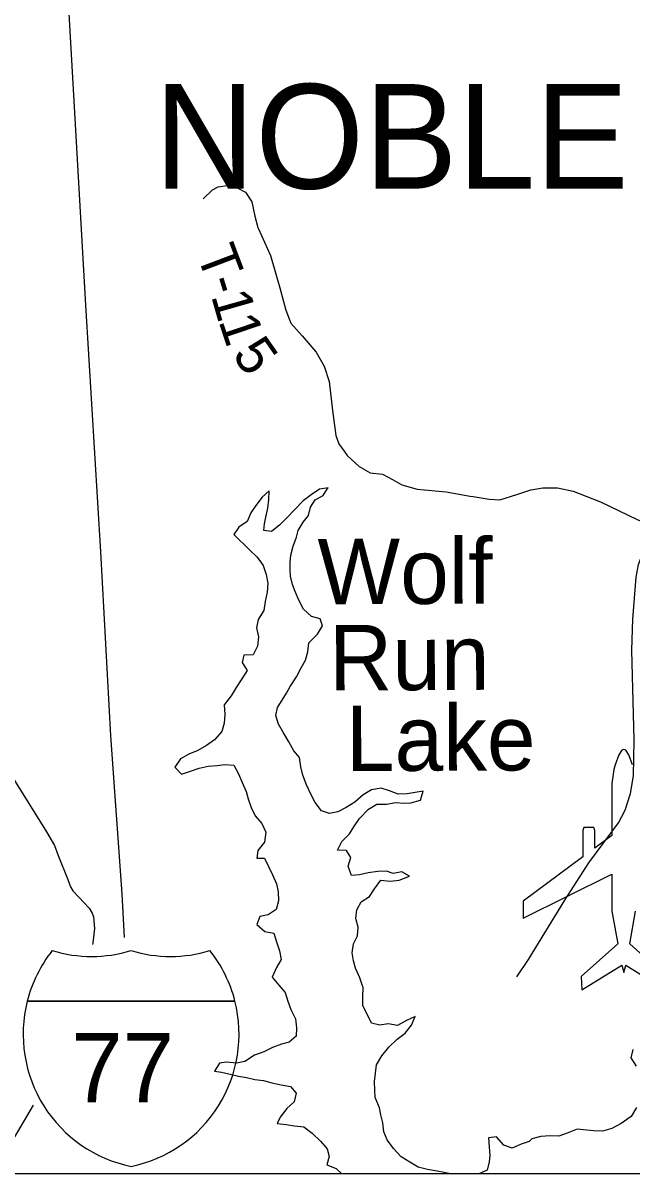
# Model space of a CAD drawing. Extents: x -22 to 431, y -18 to 160.
# Drawn here: x -7.263 to -6.381, y 14.134 to 15.801 of the extents above; entities that cross this region are included whole.
import ezdxf

# ---------------------------------------------------------------- set-up
doc = ezdxf.new("R2010")
doc.units = 0
for name, color, linetype in [('GM_X_Adjacent_County_Text', 7, 'Continuous'), ('GM_X_Airport_Location_Class_2', 7, 'Continuous'), ('GM_X_Airport_Text_Class_2', 7, 'Continuous'), ('GM_X_City_Street_Text', 7, 'Continuous'), ('GM_X_County_Road', 7, 'Continuous'), ('GM_X_County_Road_Text', 7, 'Continuous'), ('GM_X_Minor_River_Text', 7, 'Continuous'), ('GM_X_Rail_Line', 7, 'Continuous'), ('GM_X_Rail_Line_Text', 7, 'Continuous'), ('GM_X_Section', 7, 'Continuous'), ('GM_X_Township_Subdivision', 7, 'Continuous'), ('GM_X_US_Location', 7, 'Continuous')]:
    doc.layers.add(name, color=color, linetype=linetype)

msp = doc.modelspace()

# ---------------------------------------------------------------- linework, layer by layer
at = {"layer": 'GM_X_Adjacent_County_Text'}
msp.add_lwpolyline([(-6.548, 14.4201), (-6.5311, 14.4452), (-6.4782, 14.5311), (-6.4434, 14.585), (-6.4007, 14.6431), (-6.3908, 14.6613), (-6.3833, 14.6852), (-6.3788, 14.711), (-6.3781, 14.763), (-6.3816, 14.8928), (-6.3797, 14.9379), (-6.3753, 14.9986), (-6.3715, 15.0169), (-6.3639, 15.0366), (-6.3564, 15.0526), (-6.3484, 15.0696), (-6.3401, 15.0776), (-6.3299, 15.0902), (-6.3178, 15.1054), (-6.3072, 15.124), (-6.2966, 15.1471), (-6.2917, 15.1608)], dxfattribs=at)
at = {"layer": 'GM_X_County_Road'}
msp.add_lwpolyline([(-7.0018, 15.5468), (-6.9883, 15.5598), (-6.9804, 15.5641), (-6.9671, 15.5661), (-6.9539, 15.5631), (-6.9406, 15.5564), (-6.9314, 15.5424), (-6.927, 15.5216), (-6.9228, 15.5053), (-6.9218, 15.5031), (-6.9217, 15.503)], dxfattribs=at)
at = {"layer": 'GM_X_Minor_River_Text'}
for points in [[(-6.9217, 15.503), (-6.9047, 15.4645), (-6.8911, 15.4175), (-6.8822, 15.3853), (-6.8752, 15.3664), (-6.8588, 15.348), (-6.8382, 15.3246), (-6.827, 15.3042), (-6.8197, 15.2822), (-6.8149, 15.2401), (-6.8097, 15.2038), (-6.8054, 15.192), (-6.7992, 15.1829)], [(-6.7992, 15.1829), (-6.799, 15.1827), (-6.7936, 15.1747), (-6.776, 15.1589), (-6.7707, 15.1559)], [(-6.7707, 15.1559), (-6.7705, 15.1557), (-6.7601, 15.1499), (-6.7422, 15.1477), (-6.7278, 15.1403), (-6.7145, 15.1324), (-6.6921, 15.1261), (-6.6504, 15.1223), (-6.6156, 15.1161), (-6.6112, 15.1154)], [(-6.6112, 15.1154), (-6.6109, 15.1154), (-6.5879, 15.1118), (-6.5724, 15.1107), (-6.5478, 15.1185), (-6.5278, 15.1251), (-6.5104, 15.1283), (-6.4888, 15.1281), (-6.4661, 15.1233), (-6.4266, 15.1077), (-6.3738, 15.0823), (-6.3567, 15.0749), (-6.3484, 15.0696)], [(-7.3745, 14.9073), (-7.3722, 14.8891), (-7.3657, 14.8599), (-7.3597, 14.8413), (-7.3384, 14.8068), (-7.3077, 14.7586), (-7.2728, 14.7006), (-7.2288, 14.6298), (-7.2171, 14.6101), (-7.2117, 14.5956), (-7.1977, 14.5608), (-7.1939, 14.5505), (-7.1905, 14.5445), (-7.1818, 14.5354), (-7.167, 14.5195), (-7.1625, 14.5122), (-7.1605, 14.5069), (-7.1594, 14.4899), (-7.1616, 14.469), (-7.1623, 14.4666)], [(-7.2479, 14.2343), (-7.2705, 14.1953), (-7.3022, 14.1445), (-7.3071, 14.1346)]]:
    msp.add_lwpolyline(points, dxfattribs=at)
at = {"layer": 'GM_X_Rail_Line'}
msp.add_lwpolyline([(-7.1156, 14.4767), (-7.119, 14.54), (-7.1354, 14.769), (-7.1501, 15.0356), (-7.1716, 15.3925), (-7.1957, 15.8148), (-7.2107, 16.0715), (-7.2129, 16.1551), (-7.2112, 16.2064), (-7.2053, 16.2524), (-7.19, 16.3003), (-7.1742, 16.3482), (-7.1565, 16.3954), (-7.1314, 16.4556), (-7.0991, 16.5239), (-7.0753, 16.5701), (-7.0435, 16.6402), (-7.0083, 16.7161), (-7.0057, 16.721)], dxfattribs=at)
at = {"layer": 'GM_X_Rail_Line_Text'}
for p, q in [((-7.2565, 14.3847), (-6.956, 14.3847)), ((-6.956, 14.3847), (-7.2565, 14.3847)), ((-6.956, 14.3847), (-7.2565, 14.3847))]:
    msp.add_line(p, q, dxfattribs=at)
for centre, start, end in [((-7.0672, 14.3368), 141.669, 165.8066), ((-7.1633, 14.6447), 253.0091, 286.9909), ((-7.0492, 14.6447), 253.0091, 286.9909), ((-7.1453, 14.3368), 14.1934, 38.331), ((-7.0672, 14.3368), 165.8066, 258.463), ((-7.1453, 14.3368), 281.537, 14.1934)]:
    msp.add_arc(centre, 0.1953, start, end, dxfattribs=at)
at = {"layer": 'GM_X_Section'}
msp.add_line((-1.9192, 14.1345), (-8.7192, 14.1345), dxfattribs=at)
at = {"layer": 'GM_X_Township_Subdivision'}
for points in [[(-6.8209, 15.1282), (-6.8337, 15.1262), (-6.8458, 15.1177), (-6.8574, 15.1092), (-6.8698, 15.0962), (-6.8806, 15.0847), (-6.8915, 15.074), (-6.9028, 15.0647), (-6.9142, 15.0665), (-6.9131, 15.076), (-6.9113, 15.0855), (-6.9081, 15.0984), (-6.907, 15.1113), (-6.9064, 15.1239), (-6.9165, 15.1147), (-6.9255, 15.1024), (-6.933, 15.0921), (-6.9381, 15.0791), (-6.9502, 15.071), (-6.9576, 15.0603), (-6.9351, 15.0382), (-6.9236, 15.0277), (-6.9151, 15.0157), (-6.9105, 15.0028), (-6.9081, 14.99), (-6.9094, 14.9771), (-6.912, 14.9634), (-6.9141, 14.9505), (-6.9223, 14.9375), (-6.9248, 14.9253), (-6.922, 14.9121), (-6.9234, 14.8988), (-6.9297, 14.8862), (-6.9433, 14.8857), (-6.9455, 14.875), (-6.9382, 14.8637), (-6.946, 14.8515), (-6.9542, 14.8389), (-6.9613, 14.8267), (-6.9714, 14.8137), (-6.9705, 14.8), (-6.9715, 14.7871), (-6.9748, 14.775), (-6.9856, 14.7631), (-6.9969, 14.755), (-7.0097, 14.7476), (-7.0225, 14.7422), (-7.0346, 14.7356), (-7.0431, 14.7234), (-7.0332, 14.7133), (-7.0204, 14.7179), (-7.0079, 14.7219), (-6.9947, 14.7251), (-6.9818, 14.726), (-6.9705, 14.7276), (-6.9576, 14.7266), (-6.951, 14.7138), (-6.9456, 14.7013), (-6.9398, 14.6881), (-6.937, 14.6775), (-6.9324, 14.6654), (-6.9265, 14.653), (-6.917, 14.6421), (-6.9112, 14.6293), (-6.9133, 14.6148), (-6.9226, 14.603), (-6.9244, 14.5919), (-6.913, 14.5917), (-6.9072, 14.5796), (-6.9018, 14.5675), (-6.8956, 14.5547), (-6.8932, 14.543), (-6.8927, 14.5301), (-6.8964, 14.5175), (-6.908, 14.5095), (-6.9197, 14.5071), (-6.9242, 14.4956), (-6.9127, 14.4855), (-6.8998, 14.4834), (-6.8959, 14.4705), (-6.8912, 14.4577), (-6.8892, 14.4452), (-6.8959, 14.4334), (-6.9022, 14.4196), (-6.8922, 14.408), (-6.883, 14.3971), (-6.8795, 14.3846), (-6.8748, 14.3725), (-6.8682, 14.3593), (-6.8666, 14.3461), (-6.8672, 14.3339), (-6.8773, 14.3251), (-6.8887, 14.3223), (-6.9015, 14.3177), (-6.9139, 14.3114), (-6.9275, 14.3064), (-6.9414, 14.2975), (-6.9535, 14.2947), (-6.9683, 14.2964), (-6.9781, 14.2948), (-6.9856, 14.2834)], [(-6.7702, 14.4048), (-6.7714, 14.4067), (-6.7753, 14.4187), (-6.7815, 14.4327), (-6.7843, 14.4433), (-6.7863, 14.4547), (-6.7845, 14.4679), (-6.7786, 14.4794), (-6.7776, 14.4919), (-6.7807, 14.5044), (-6.7797, 14.5169), (-6.773, 14.5284), (-6.761, 14.5361), (-6.7539, 14.5475), (-6.7446, 14.5598), (-6.7313, 14.5584), (-6.7181, 14.5601), (-6.703, 14.5655), (-6.7144, 14.5719), (-6.7269, 14.5694), (-6.7364, 14.5731), (-6.7493, 14.5726), (-6.7632, 14.5706), (-6.7757, 14.5678), (-6.7874, 14.5665), (-6.7921, 14.5801), (-6.7881, 14.5927), (-6.7946, 14.6028), (-6.8075, 14.6035), (-6.8012, 14.6157), (-6.79, 14.6272), (-6.7836, 14.6371), (-6.7758, 14.6493), (-6.7627, 14.6627), (-6.7506, 14.6701), (-6.7366, 14.6702), (-6.723, 14.6723), (-6.7109, 14.6716), (-6.7011, 14.6721), (-6.6875, 14.6757), (-6.6834, 14.689), (-6.6952, 14.687), (-6.7065, 14.685), (-6.7197, 14.6844), (-6.7323, 14.6892), (-6.7444, 14.6933), (-6.7584, 14.6908), (-6.7705, 14.6835), (-6.7825, 14.6731), (-6.7949, 14.665), (-6.8069, 14.6588), (-6.819, 14.6564), (-6.8304, 14.6601), (-6.84, 14.6725), (-6.8462, 14.6846), (-6.8524, 14.6982), (-6.8575, 14.7121), (-6.8606, 14.7239), (-6.8623, 14.7375), (-6.8707, 14.7473), (-6.878, 14.7601), (-6.8858, 14.7733), (-6.8927, 14.7857), (-6.8966, 14.7982), (-6.8945, 14.81), (-6.8878, 14.8207), (-6.8814, 14.8306), (-6.8758, 14.8405), (-6.8669, 14.8543), (-6.8602, 14.8672), (-6.8539, 14.8787), (-6.8506, 14.8908), (-6.8492, 14.9037), (-6.8365, 14.916), (-6.8294, 14.9282), (-6.8326, 14.9384), (-6.8451, 14.9417), (-6.8566, 14.9526), (-6.8635, 14.9654), (-6.8689, 14.9779), (-6.8728, 14.9881), (-6.8756, 15.0002), (-6.8761, 15.01), (-6.8758, 15.0199), (-6.8752, 15.0305), (-6.8715, 15.0435), (-6.8667, 15.0564), (-6.8642, 15.0663), (-6.8571, 15.0785), (-6.8496, 15.0881), (-6.8467, 15.0999), (-6.84, 15.1109), (-6.828, 15.1168), (-6.822, 15.1271), (-6.8209, 15.1282)], [(-6.6437, 14.1345), (-6.6531, 14.1364), (-6.6634, 14.1386), (-6.6774, 14.1411), (-6.6907, 14.1444), (-6.7029, 14.1515), (-6.7151, 14.1593), (-6.7266, 14.1713), (-6.7358, 14.1841), (-6.7405, 14.1954), (-6.7417, 14.2083), (-6.7445, 14.22), (-6.7465, 14.2302), (-6.7531, 14.2453), (-6.7532, 14.2556), (-6.7537, 14.2684), (-6.7527, 14.2806), (-6.7509, 14.2927), (-6.7435, 14.3057), (-6.733, 14.3183), (-6.721, 14.3298), (-6.7094, 14.3383), (-6.7004, 14.3498), (-6.6948, 14.3627), (-6.7076, 14.3565), (-6.7208, 14.3496), (-6.7341, 14.3517), (-6.7462, 14.35), (-6.7584, 14.353), (-6.7645, 14.3658), (-6.7707, 14.3778), (-6.7709, 14.3911), (-6.7702, 14.4048)], [(-6.3797, 14.3146), (-6.383, 14.3028), (-6.3753, 14.2904)], [(-6.9856, 14.2834), (-6.9754, 14.282), (-6.9628, 14.2791), (-6.9507, 14.2762), (-6.9393, 14.274), (-6.9272, 14.2711), (-6.9146, 14.2697), (-6.9025, 14.2665), (-6.8892, 14.2636), (-6.8756, 14.2611), (-6.8675, 14.2513), (-6.8704, 14.2387), (-6.8809, 14.2291), (-6.8906, 14.2169), (-6.8947, 14.2074), (-6.8818, 14.206), (-6.8697, 14.2042), (-6.856, 14.2025), (-6.8442, 14.1935), (-6.8323, 14.1819), (-6.8224, 14.171), (-6.8196, 14.1597), (-6.8229, 14.1479), (-6.8096, 14.1423), (-6.8013, 14.1345)], [(-6.3746, 14.2308), (-6.3825, 14.2179), (-6.3967, 14.2075), (-6.4103, 14.2005), (-6.4239, 14.1966), (-6.4368, 14.1968), (-6.4466, 14.1978), (-6.4603, 14.1992), (-6.475, 14.1937), (-6.4871, 14.1894), (-6.4996, 14.1897), (-6.5132, 14.1888), (-6.526, 14.1852)], [(-6.526, 14.1852), (-6.5301, 14.1814), (-6.5415, 14.1778), (-6.5547, 14.1716), (-6.5668, 14.1761), (-6.5775, 14.1881), (-6.5889, 14.1868), (-6.588, 14.1739), (-6.5871, 14.1614), (-6.5878, 14.1519), (-6.5907, 14.1398), (-6.6027, 14.1347), (-6.6045, 14.1345)]]:
    msp.add_lwpolyline(points, dxfattribs=at)
at = {"layer": 'GM_X_US_Location'}
for points in [[(-6.3805, 14.7271), (-6.3856, 14.7416), (-6.3903, 14.7481), (-6.393, 14.7492), (-6.3957, 14.7481), (-6.4004, 14.7416), (-6.4055, 14.7271), (-6.4076, 14.72), (-6.4101, 14.7001), (-6.4101, 14.6247), (-6.4348, 14.6064), (-6.4348, 14.6317), (-6.4362, 14.6363), (-6.4509, 14.6363), (-6.4522, 14.6317), (-6.4522, 14.5935), (-6.5387, 14.5296), (-6.5387, 14.5051), (-6.4101, 14.5685), (-6.4101, 14.5151), (-6.4015, 14.4679), (-6.4545, 14.4204), (-6.4536, 14.4009), (-6.3957, 14.4368), (-6.393, 14.4263), (-6.3903, 14.4368), (-6.3324, 14.4009)], [(-6.3315, 14.4204), (-6.3844, 14.4679), (-6.3759, 14.5151)]]:
    msp.add_lwpolyline(points, dxfattribs=at)

# ---------------------------------------------------------------- texts
at = {"layer": 'GM_X_Airport_Location_Class_2'}
msp.add_text('77', height=0.1, dxfattribs=at).set_placement((-7.193, 14.2384))
at = {"layer": 'GM_X_Airport_Text_Class_2'}
for s, rotation, p in [('Wolf', 0.2496, (-6.8361, 14.9593)), ('Run', 0.2492, (-6.8195, 14.8346)), ('Lake', 0.2482, (-6.7952, 14.7178))]:
    msp.add_text(s, height=0.0947, rotation=rotation, dxfattribs=at).set_placement(p)
at = {"layer": 'GM_X_City_Street_Text'}
for s, rotation, p in [('T', 290.7055, (-7.0122, 15.4671)), ('-', 286.9759, (-6.9975, 15.4283)), ('1', 285.9361, (-6.9907, 15.4063)), ('1', 288.6406, (-6.9802, 15.3698)), ('5', 304.9988, (-6.9611, 15.3209))]:
    msp.add_text(s, height=0.0568, rotation=rotation, dxfattribs=at).set_placement(p)
at = {"layer": 'GM_X_County_Road_Text'}
msp.add_text('NOBLE', height=0.15152, rotation=0, dxfattribs=at).set_placement((-7.0729, 15.5613))

doc.saveas('drawing.dxf')
